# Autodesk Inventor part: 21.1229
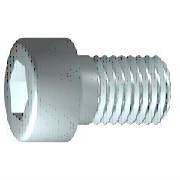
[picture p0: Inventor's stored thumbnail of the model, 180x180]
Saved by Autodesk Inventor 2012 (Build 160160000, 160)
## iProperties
IsCustomPart: 1
Created: 2006-02
Part Number: 21.1229
Material: Steel, Mild
Description: M4X12 SHCS ZINC PLATED DIN 7984
Document SubType Name: Modeling
Standard: DIN 7984
Designer: Andy Moles
Standards Organization: DIN
Language: en-US
Size Designation: M4 x 12
Categories: <MemberInstance><Categories><Category DisplayName="Fasteners" InternalName="e4da775c-781d-43d5-af7c-5136215cf5a6" Mnemonic="FSTN"><Category DisplayName="Bolts"
Density: 7.86 g/cm^3
Mass: 1.90624 g
Surface Area: 3.03485 cm^2
Volume: 0.242524 cm^3
Vendor: S
Title: M4x12 SHCS ZINC PLATED
Author: Andy Moles
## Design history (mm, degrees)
workplane "Work Plane1"
revolve "Body" stored, may be unused: angle "d10" = 90 deg
sketch "Sketch2"
  geometry: L1 (0, -4.2)-(0, 5.6) reference; L2 (-4.2, 0)-(5.6, 0) reference; L3 (1.443, 0)-(0.722, -1.25); L4 (0.722, -1.25)-(-0.722, -1.25); L5 (-0.722, -1.25)-(-1.443, 0); L6 (-1.443, 0)-(-0.722, 1.25); L7 (-0.722, 1.25)-(0.722, 1.25); L8 (0.722, 1.25)-(1.443, 0); 2 further points
  constraints: 12 end point, 1 coincident, 1 horizontal alignment, 1 point on line, 12 other
extrude "Slot" join sketch "Sketch2" stored distance "d11" = 10; taper "d12" = 0 deg
body "Solid1"
fillet "Fillet1" dims "d17" = 0.4 (= RR)
feature "Thread" dims "d13" = 12, "d14" = 0
chamfer "Chamfer1" distance "d15" = 0.42941 (= -0.5 x SPD + 0.5 x GD); stored, may be unused: second distance "d16" = 0.42941 (= GUL), angle "d27" = 45 deg
sketch "Sketch1"
  geometry: L1 (0.333, 0)-(12, 0); L2 (12, 0)-(12, 2); L3 (12, 2)-(2.1, 2); L4 (2.1, 2)-(1.67, 2); L5 (1.67, 2)-(0, 2); L6 (0, 2)-(0, 3.5); L7 (0, 3.5)-(-2.8, 3.5); L8 (-2.8, 3.5)-(-2.8, 1.443); L9 (-2.8, 1.443)-(-0.5, 1.443); L10 (-0.5, 1.443)-(0.333, 0); L11 (-4.28, 0)-(16.44, 0) reference; L12 (0, -0.35)-(0, 4.55) reference; L13 (2.1, 2)-(0, 2)
  constraints: 22 end point, 6 parallel, 2 collinear, 2 perpendicular, 1 horizontal, 1 point on line
  dimensions: "d1" = 9.9 distance from line of L3.end L2 (= GEL); "d2" = 0.42952 distance of L4.end L3.end (computed from GAL); "d3" = 2.8 distance between parallel lines of L8 L6 (= KOH); "d4" = 2.3 distance of L8.end L9.end (= INTI); "d5" = 60 deg angle of L10 L1; "d6" = 4 diameter of L3 L1 (= GD); "d7" = 4 diameter of L5 L1 (= BDM); "d8" = 2.88675 diameter of L9 L1 (= 1.1547 x SW); "d9" = 7 diameter of L7 L1 (= KOD); "d26" = 12 distance between parallel lines of L12 L2 (= NLG)
other parameters: "GD" = 4 (= NND) [user parameter; used in 2 equation terms], "NLG" = 12 [user parameter; used in 1 equation term], "GEL" = 9.9 [user parameter; used in 1 equation term], "KOD" = 7 [user parameter; used in 1 equation term], "KOH" = 2.8 [user parameter; used in 1 equation term], "INTI" = 2.3 [user parameter; used in 1 equation term], "GAL" = 0.42941 (= 0.61345 x PTC) [user parameter; used in 1 equation term], "GUL" = 0.42941 (= 0.61345 x PTC) [user parameter; used in 1 equation term], "BDM" = 4 (= NND) [user parameter; used in 1 equation term], "SW" = 2.5 [user parameter; used in 2 equation terms], "RR" = 0.4 [user parameter; used in 1 equation term], "SPD" = 3.14117 (= NND - 1.2269 x PTC) [user parameter; used in 1 equation term], "d19" = 0, "d28" = 0, "d29" = 0, "TOA" = 30 deg [user parameter], "GD1" = 3.14117 (= THREADDIA - 1.2269 x PTC) [user parameter], "THREADDIA" = 4 [user parameter; used in 1 equation term], "FAWI" = 45 deg [user parameter], "ANG" = 120 deg [user parameter], "TPU" = 14.28571 (computed from PTC) [user parameter], "PTC" = 0.7 [user parameter; used in 5 equation terms], "NND" = 4 [user parameter; used in 3 equation terms], "E0" = 2.8875 (= 1.155 x SW) [user parameter]
